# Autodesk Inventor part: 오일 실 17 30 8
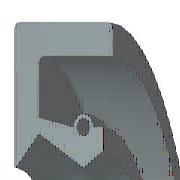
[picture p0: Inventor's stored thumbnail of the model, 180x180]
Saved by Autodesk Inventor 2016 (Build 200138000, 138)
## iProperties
IsCustomPart: 1
Created: 2012-02
Part Number: 오일 실 17 30 8
Material: 고무
Description: 오일-실
Document SubType Name: Modeling
Standard: KS B 2804
Designer: mduedu
Standards Organization: KS
Language: ko-KR
Size Designation: D - 17 30 8
Categories: <MemberInstance><Categories><Category DisplayName="샤프트 부품" InternalName="7f7aeb1f-a693-4053-b835-cee3144e0d98" Mnemonic="SHFT"><Category DisplayName="실링" Intern
Density: 0.93 g/cm^3
Appearance: 고무 - 검은색 - 버전 1.1
Author: mduedu
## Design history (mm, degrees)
revolve "본체" stored, may be unused: angle "d17" = 90 deg
revolve "스프링1" stored, may be unused: angle "d18" = 90 deg
body "Solid1"
sketch "스케치1"
  geometry: L1 (0, 15)-(8, 15); L2 (8, 13.25)-(1.75, 13.25); L3 (1.75, 10.25)-(4.9, 8.5); L4 (4.9, 8.5)-(0, 8.5); L5 (0, 0)-(9.586, 0) reference; L6 (4.9, 8.5)-(6.3, 9.375); L7 (0, 18)-(0, -3) reference; L8 (-1.941, 0)-(11.507, 0) reference; L9 (4.2, 10.6)-(1.75, 11.21); L10 (1.75, 11.21)-(1.75, 13.25); L11 (0, 15)-(0, 8.588); L12 (4.9, 8.5)-(0, 8.5); L13 (1.75, 10.25)-(0.152, 8.528); L14 (8, 15)-(8, 13.25); L15 (5.6, 10.6)-(6.3, 10.6); L16 (6.3, 10.6)-(6.3, 9.375); C1 r 0.455 at (4.9, 10.6); A1 r 0.7 centre (4.9, 10.6) between (5.6, 10.6) and (4.2, 10.6); A2 r 0.088 centre (0.088, 8.588) between (0, 8.588) and (0.152, 8.528); 1 further point
  constraints: 28 end point, 5 horizontal alignment, 5 point on line, 4 point on circle, 4 vertical alignment, 3 centre point, 3 tangent, 2 collinear, 2 horizontal, 2 perpendicular, 1 coincident, 1 parallel
  dimensions: "d0" = 30 diameter of L1 L5 (= SD2); "d1" = 1.75 distance of L1.end L2.start (= SD); "d2" = 0.91 diameter of C1 (= SPDI); "d3" = 1.4 diameter of A1 (= SPDA); "d4" = 17 diameter of L3.end L5 (= NND); "d5" = 20.5 diameter of L3.start L5 (= TKDM); "d7" = 22.42 diameter of L9.end L5 (= TKDM + 0.24 x SWDT); "d8" = 1.75 distance between parallel lines of L11 L10 (= SD); "d9" = 4.9 distance from line of L11 C1.centre (= SPDST); "d10" = 21.2 diameter of C1.centre L5 (= HLDM); "d11" = 0.0875 radius of A2 (= 0.25 x LAB); "d12" = 6.3 distance between parallel lines of L11 L16 (= SDI); "d13" = 18.75 diameter of L6.end L5 (= ABDM); "d14" = 8 distance from line of L11 L1.end (= SWDT)
fillet "모깎기1" dims "d6" = 0.3 (= RR)
other parameters: "SD2" = 30 [user parameter; used in 1 equation term], "SWDT" = 8 [user parameter; used in 2 equation terms], "RR" = 0.3 [user parameter; used in 1 equation term], "SD" = 1.75 [user parameter; used in 2 equation terms], "NND" = 17 [user parameter; used in 1 equation term], "SPDA" = 1.4 [user parameter; used in 1 equation term], "SPDI" = 0.91 [user parameter; used in 1 equation term], "TKDM" = 20.5 [user parameter; used in 2 equation terms], "HLDM" = 21.2 [user parameter; used in 1 equation term], "ABDM" = 18.75 [user parameter; used in 1 equation term], "SDI" = 6.3 [user parameter; used in 1 equation term], "SPDST" = 4.9 [user parameter; used in 1 equation term], "LAB" = 0.35 [user parameter; used in 1 equation term], "d15" = 0, "d16" = 0, "d19" = 0
